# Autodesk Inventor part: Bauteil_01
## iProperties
Created: 2007-04
Part Number: Bauteil_01
Document SubType Name: Modeling
Designer: Sascha Fleischer
Author: Sascha Fleischer
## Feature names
1. Extrusion1
